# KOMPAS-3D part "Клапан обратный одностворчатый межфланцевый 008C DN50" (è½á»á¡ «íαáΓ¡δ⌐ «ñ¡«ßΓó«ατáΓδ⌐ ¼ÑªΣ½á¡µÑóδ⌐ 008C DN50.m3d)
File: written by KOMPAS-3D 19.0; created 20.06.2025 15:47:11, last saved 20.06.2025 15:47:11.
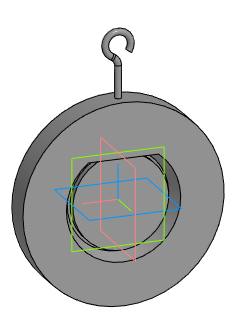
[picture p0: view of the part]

Document properties: Полное имя файла: E:\Dendor Работа Сачек\3D для проектировщиков\5.1 Тип 008C. Клапан обратный одностворчатый межфланцевый\stp_Клапан обратный одностворчатый межфланцевый 008C\Клапан обратный одностворчатый межфланцевый 008C DN50.m3d

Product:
- Part/product: Клапан обратный одностворчатый межфланцевый 008C DN50

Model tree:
1. Операция без истории:1  (labels: Клапан обратный одностворчатый межфланцевый 008C DN50)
